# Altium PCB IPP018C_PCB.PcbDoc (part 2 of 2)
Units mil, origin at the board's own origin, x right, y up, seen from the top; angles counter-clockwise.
Board outline 3500 x 2700 mil, 4 copper layers (Top Layer, Mid-Layer 1, Mid-Layer 2, Bottom Layer), stack 90 mil thick; 62 components, 59 nets, 295 pads, 117 vias.
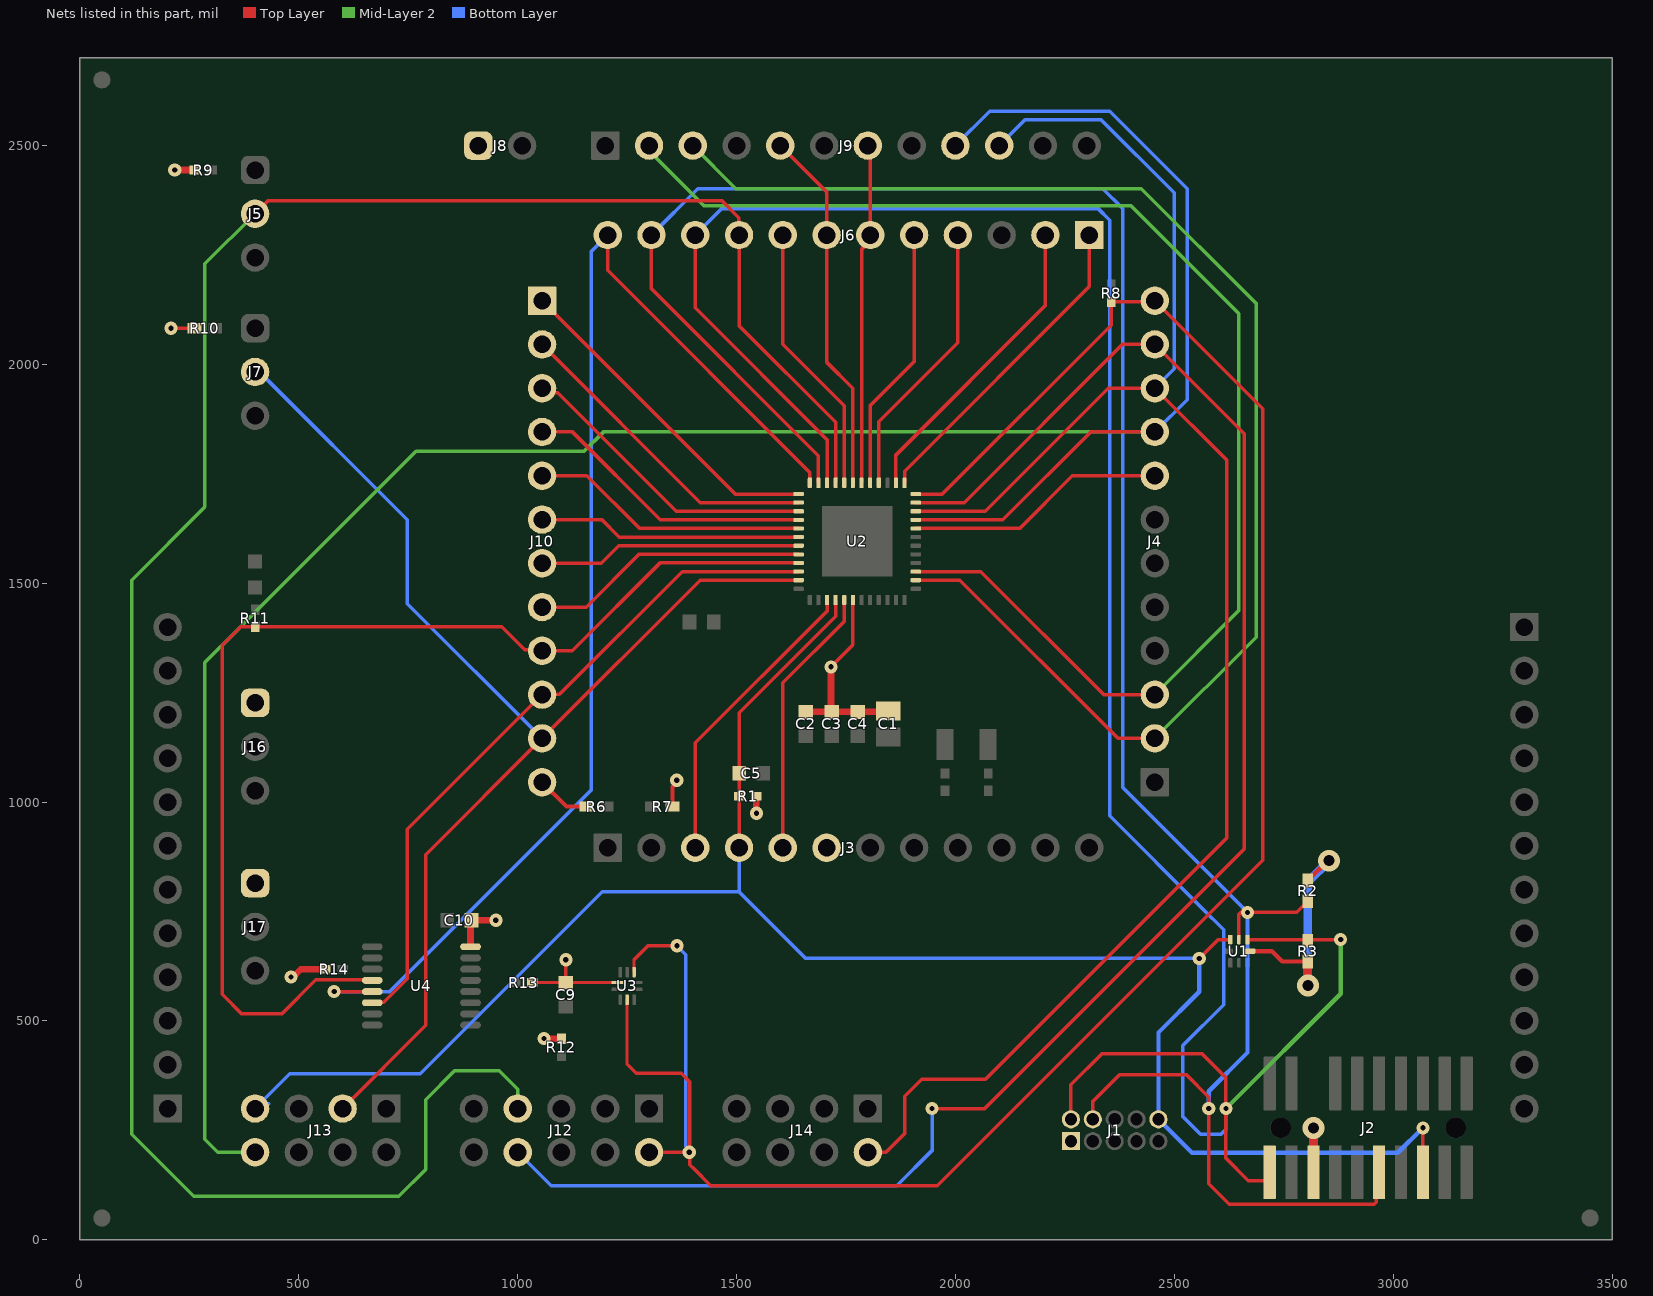
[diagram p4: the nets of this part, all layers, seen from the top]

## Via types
v1: diameter 30, hole 12, Top Layer to Bottom Layer, 102 vias
v2: diameter 19.68, hole 7.87, Top Layer to Bottom Layer, tented both sides, 12 vias
v3: diameter 50, hole 25, Top Layer to Bottom Layer, 2 vias
v4: diameter 50, hole 25, Top Layer to Bottom Layer, tented both sides, 1 vias

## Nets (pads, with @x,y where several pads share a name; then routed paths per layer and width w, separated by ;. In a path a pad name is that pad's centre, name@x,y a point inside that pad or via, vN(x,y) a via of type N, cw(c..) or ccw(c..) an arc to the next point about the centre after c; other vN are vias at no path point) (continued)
"PA13 UART3_RX": J6.4 U2.28 | length 641
  Top Layer w8: U2.28@1824.8,1729.45 1824.8,1868.75 2005.59,2049.54 J6.4@2005.59,2295.59
"PA14 UART3_TX": J6.5 U2.29 | length 607.8
  Top Layer w8: U2.29@1805.12,1729.45 1805.12,1906.14 1905.59,2006.61 J6.5@1905.59,2295.59
"PA15 I2C1_SCL": J6.6 J9.7 U2.30 | length 781.2
  Top Layer w8: U2.30@1785.43,1729.45 1785.43,2262.42 1805.59,2282.58 1805.59,2494.41 J9.7@1800,2500
"PA16 I2C1_SDA": J6.7 J9.5 U2.31 | length 839.2
  Top Layer w8: J9.5@1600,2500 1705.59,2394.41 J6.7@1705.59,2295.59 1705.59,2005.52 1765.75,1945.36 U2.31@1765.75,1729.45
PA17/A1_2: J6.8 U2.32 | length 624.3
  Top Layer w8: J6.8@1605.59,2295.59 1605.59,2046.09 1746.06,1905.62 U2.32@1746.06,1729.45
"PA18/A1_3 BSL SEL": J5.2 J6.9 J12.7 U2.33 | length 5265
  Top Layer w8: J5.2@400,2344.09 430.3,2374.39 1466.14,2374.39 1505.15,2335.38 1505.15,2296.04 J6.9@1505.59,2295.59 1505.59,2088.44 1726.38,1867.65 U2.33@1726.38,1729.45
  Mid-Layer 2 w8: J5.2@400,2344.09 285.43,2229.53 285.43,1674.31 118.11,1506.99 118.11,241.11 259.73,99.49 728.35,99.49 789.66,160.81 789.66,319.98 855.71,386.03 957.92,386.03 1000,343.95 J12.7@1000,300
"PA19 SWDIO": J1.2 J2.1 J6.10 R3.2 U1.1 U2.34 | length 5539.2
  Top Layer w8: J6.10@1405.59,2295.59 1405.59,2129.36 1706.69,1828.26 U2.34@1706.69,1729.45 ; J1.2@2263.8,275.42 2263.8,354 2335.36,425.56 2563.02,425.56 2618.11,370.47 v1(2618.11,300) 2618.11,186.22 2669.17,135.16 J2.1@2721.65,135.16 ; U1.1@2667.32,686.02 2802.17,686.02 R3.2@2805.12,683.07 2808.07,686.02 v1(2880.12,686.02)
  Mid-Layer 2 w10: v1(2618.11,300) 2880.12,562.01 v1(2880.12,686.02)
  Bottom Layer w8: J6.10@1405.59,2295.59 1466.04,2356.04 2325.75,2356.04 2352.36,2329.43 2352.36,968.52 2562.76,758.12 2612.85,708.03 2612.85,537.11 2519.68,443.94 2519.68,281.63 2559.92,241.39 2606.81,241.39 2618.11,252.69 v1(2618.11,300)
"PA20 SWCLK": J1.4 J2.11 J6.11 R2.2 U1.2 U2.35 | length 5326.7
  Top Layer w8: J6.11@1305.59,2295.59 1305.59,2172.75 1687.01,1791.34 U2.35@1687.01,1729.45 ; J1.4@2313.8,275.42 2314.24,275.85 2314.24,316.2 2374.94,376.91 2527.96,376.91 2578.74,326.13 v1(2578.74,300) 2578.74,127.95 2625.65,81.04 2956.6,81.04 2961.28,85.73 2961.28,147.8 J2.11@2967.91,154.43 ; U1.2@2647.64,686.02 2647.64,743.35 2652.32,748.03 v1(2667.32,748.03) 2779.53,748.03 R2.2@2805.12,773.62
  Bottom Layer w8: J6.11@1305.59,2295.59 1411.57,2401.57 2336.36,2401.57 2381.89,2356.04 2381.89,1033.46 v1(2667.32,748.03)
  Bottom Layer w10: v1(2578.74,300) 2578.74,339.35 2667.32,427.93 v1(2667.32,748.03)
PA21/A1_7/VREF-: J10.3 U2.39 | length 702.6
  Top Layer w8: J10.3@1055.59,1945.59 1066.23,1934.95 1091.86,1934.95 1362.33,1664.49 U2.39@1641.73,1664.49
PA22/A0_7: J10.4 U2.40 | length 669.3
  Top Layer w8: J10.4@1055.59,1845.59 1125.2,1845.59 1325.98,1644.8 U2.40@1641.73,1644.8
"PA23 VREF+": J10.7 U2.43 | length 602.8
  Top Layer w8: J10.7@1055.59,1545.59 1191.06,1545.59 1231.22,1585.75 U2.43@1641.73,1585.75
PA24/A0_3: J10.8 U2.44 | length 636
  Top Layer w8: J10.8@1055.59,1445.59 1156.5,1445.59 1276.97,1566.06 U2.44@1641.73,1566.06
"PA25 GUARDBAND": J10.9 R11.2 U2.45 U4.4 | length 2632.7
  Top Layer w8: U4.4@667.8,592.8 667.8,594.08 538.68,594.08 460.63,516.02 369.8,516.02 324.8,561.02 324.8,1358.27 366.85,1400.32 R11.2@400,1400.32 963.54,1400.32 1015.8,1348.06 1053.12,1348.06 J10.9@1055.59,1345.59 1124.39,1345.59 1325.18,1546.38 U2.45@1641.73,1546.38
"PA26/A0_1 INT TO HOST": J10.10 U2.46 U4.6 | length 1581.9
  Top Layer w8: U4.6@667.8,541.61 669.16,542.98 694.28,542.98 747.72,596.42 747.72,937.72 1056.09,1246.09 1095.38,1246.09 1375.98,1526.69 U2.46@1641.73,1526.69
"PA27/A0_0 I2C or UART/SPI": J7.2 J10.11 J13.3 U2.47 | length 2884.7
  Top Layer w8: J13.3@600,300 790,490 790,880 J10.11@1055.59,1145.59 1417.01,1507.01 U2.47@1641.73,1507.01
  Bottom Layer w8: J7.2@400,1982.7 410.12,1982.7 748.03,1644.79 748.03,1453.15 J10.11@1055.59,1145.59
"PA28 UART0_TX": J3.3 U2.3 | length 690.9
  Top Layer w8: J3.3@1405.59,895.59 1405.59,1135.23 1706.69,1436.33 U2.3@1706.69,1461.73
"PA31 UART0_RX": J3.5 U2.5 | length 624.3
  Top Layer w8: J3.5@1605.59,895.59 1605.59,1272.28 1746.06,1412.76 U2.5@1746.06,1461.73
"PB2 RESET": J4.2 J9.3 U2.14 | length 3221.8
  Top Layer w8: U2.14@1909.45,1507.01 2010.12,1507.01 2371.54,1145.59 J4.2@2455.59,1145.59
  Mid-Layer 2 w8: J9.3@1400,2500 1498.43,2401.57 2424.64,2401.57 2687.01,2139.21 2687.01,1377.01 J4.2@2455.59,1145.59
"PB3 OSS": J4.3 J9.2 U2.15 | length 3126.2
  Top Layer w8: U2.15@1909.45,1526.69 2058.18,1526.69 2339.28,1245.59 J4.3@2455.59,1245.59
  Mid-Layer 2 w8: J9.2@1300,2488.19 1426.24,2361.95 2401.83,2361.95 2647.64,2116.14 2647.64,1437.64 J4.3@2455.59,1245.59
  Bottom Layer w8: J9.2@1300,2488.19 J9.2@1300,2500
"PB6 SPI1_CS0": J4.8 U2.20 | length 596
  Top Layer w8: U2.20@1909.45,1625.12 2146.54,1625.12 2267.01,1745.59 J4.8@2455.59,1745.59
"PB7 PG1": J4.9 J9.9 J13.8 U2.21 | length 5455.9
  Top Layer w8: U2.21@1909.45,1644.8 2108.5,1644.8 2309.29,1845.59 J4.9@2455.59,1845.59
  Mid-Layer 2 w8: J13.8@400,200 314.96,200 285.43,229.53 285.43,1318.9 767.72,1801.18 1151.57,1801.18 1195.98,1845.59 J4.9@2455.59,1845.59
  Bottom Layer w8: J9.9@2000,2500 2078.74,2578.74 2352.36,2578.74 2529.53,2401.57 2529.53,1919.53 J4.9@2455.59,1845.59
"PB8 PG2": J4.10 J9.10 J14.2 U2.22 | length 3883.9
  Top Layer w8: J14.2@1800,200 1841.33,200 1884.17,242.84 1884.17,328.26 1923.02,367.11 2068.56,367.11 2620.33,918.88 2620.33,1780.85 J4.10@2455.59,1945.59 2349.13,1945.59 2068.03,1664.49 U2.22@1909.45,1664.49
  Bottom Layer w8: J9.10@2100,2500 2159.06,2559.06 2332.68,2559.06 2499.94,2391.79 2499.94,1989.94 J4.10@2455.59,1945.59
"PB9 SPI1_SCK": J4.11 J12.8 U2.23 | length 3999.3
  Top Layer w8: U2.23@1909.45,1684.17 2020.27,1684.17 2381.69,2045.59 J4.11@2455.59,2045.59 2659.7,1841.48 2659.7,892.99 2066.75,300.03 v1(1946.5,300.03)
  Bottom Layer w8: J12.8@1000,200 1076.48,123.52 1865.97,123.52 1946.5,204.04 v1(1946.5,300.03)
"PB14 SPI1_POCI": J4.12 J12.2 R8.1 U2.24 U3.4 U3.8 | length 4985.1
  Top Layer w7: 1250,401.22 U3.4@1250,548.5 ; U3.8@1265.75,611.5 1265.75,640
  Top Layer w8: 1250,401.22 1270.92,380.3 1373.39,380.3 1392.6,361.09 1392.6,172.36 ; 1265.75,640 1297.54,671.8 v1(1363.64,671.8) ; J12.2@1300,200 v1(1391.8,200) ; 1393.16,171.8 1402.69,162.27 1441.44,123.52 1958.71,123.52 2702.29,867.1 2702.29,1898.89 J4.12@2455.59,2145.59 ; U2.24@1909.45,1703.86 1969.84,1703.86 2355.59,2089.61 R8.1@2355.59,2143.28 J4.12@2453.28,2143.28
  Bottom Layer w8: v1(1363.64,671.8) 1384.17,651.27 1384.17,213.58 1391.8,205.95 v1(1391.8,200)
"PB15 SPI1_PICO/UART2_TX": J6.1 U2.25 | length 740.8
  Top Layer w8: U2.25@1883.86,1729.45 1883.86,1756.3 2305.59,2178.04 J6.1@2305.59,2295.59
"PB16 MUX_C": J6.2 U2.26 | length 707.6
  Top Layer w8: U2.26@1864.17,1729.45 1864.17,1793.08 2205.59,2134.5 J6.2@2205.59,2295.59
"PB17/A1_4 RESERVED": J6.12 U2.36 U4.5 | length 2905.9
  Top Layer w8: v1(580.71,567.2) U4.5@667.8,567.2 ; J6.12@1205.59,2295.59 1205.59,2214.82 1667.32,1753.09 U2.36@1667.32,1729.45
  Bottom Layer w8: v1(580.71,567.2) 707.35,567.2 1168.48,1028.34 1168.48,2258.48 J6.12@1205.59,2295.59
PB18/A1_5: J10.1 U2.37 | length 769.1
  Top Layer w8: J10.1@1055.59,2145.59 1084.07,2117.11 1497.32,1703.86 U2.37@1641.73,1703.86
PB19/A1_6: J10.2 U2.38 | length 735.8
  Top Layer w8: J10.2@1055.59,2045.59 1417.01,1684.17 U2.38@1641.73,1684.17
PB20/A0_6: J10.5 U2.41 | length 636
  Top Layer w8: J10.5@1055.59,1745.59 1157.95,1745.59 1278.43,1625.12 U2.41@1641.73,1625.12
PB24/A0_5: J10.6 U2.42 | length 602.8
  Top Layer w8: J10.6@1055.59,1645.59 1191.97,1645.59 1232.13,1605.43 U2.42@1641.73,1605.43
RST: C5.1 J1.10 J2.15 J3.4 J13.7 R1.1 U1.3 U2.4 | length 4474.6
  Top Layer w8: J3.4@1505.59,895.59 1505.91,895.91 R1.1@1505.91,1013.78 C5.1@1505.91,1065.59 1505.91,1204.53 1726.38,1425 U2.4@1726.38,1461.73 ; v1(2557.1,642.85) 2600.28,686.02 U1.3@2627.95,686.02 ; J2.15@3067.91,138.9 v1(3067.91,255.91)
  Bottom Layer w8: J13.7@400,300 J13.7@410.9,310.9 ; 430.94,310.9 J13.7@410.9,310.9 ; J3.4@1505.59,895.59 1505.59,795.58 ; v1(2557.1,642.85) 1658.33,642.85 1505.59,795.58 ; J13.7@410.9,310.9 479.61,379.61 777.13,379.61 1193.1,795.58 1505.59,795.58
  Bottom Layer w10: v1(2557.1,642.85) 2557.1,566.94 2463.8,473.65 J1.10@2463.8,275.42 2540.46,198.76 3010.77,198.76 v1(3067.91,255.91)
VDD: C1.2 C2.2 C3.2 C4.2 C9.2 C10.2 J1.1 J2.5 J3.6 J8.1 J10.12 J16.1 J17.1 R1.2 R2.1 R3.1 R6.2 R7.2 R9.2 R10.1 R12.1 R13.2 R14.2 U1.8 U2.6 U3.1 U4.16 | length 1970.8
  Top Layer w7: R13.2@1033.78,587.56 C9.2@1110,587.56 ; C9.2@1110.32,587.87 U3.1@1228.35,587.87
  Top Layer w8: v1(207.99,2082.7) R10.1@261.81,2082.7 ; C10.2@892.2,728.03 C10.2@894.17,730 ; R13.2@1033.46,587.87 R13.2@1033.78,587.56 ; v1(1060,460) v1@1060.32,459.68 ; v1(1110,640) C9.2@1110,587.56 C9.2@1110.32,587.87 ; v1(1715.8,1309.06) 1765.75,1359.01 U2.6@1765.75,1461.73
  Top Layer w10: J10.12@1055.59,1045.59 1111.34,989.84 R6.2@1156.38,989.84 ; R7.2@1353.62,989.84 1353.62,1034.89 1363.38,1044.65 v1(1363.38,1050.06) ; U1.8@2673.23,659.45 2723.03,659.45 2746.65,635.83 R3.1@2805.12,635.83 ; R2.1@2805.12,820.87 2850.39,866.14 v3(2853.74,866.14)
  Top Layer w15: v1(216.5,2444.09) R9.2@261.81,2444.09 ; v1(482.28,600.39) 486.34,600.39 504.33,618.39 R14.2@561.02,618.39 ; U4.16@892.2,669.57 C10.2@892.2,728.03 ; C10.2@894.17,730 v1(950,730) ; v1@1060.32,459.68 R12.1@1100,459.68 ; v1(1545.28,974.41) R1.2@1545.28,1013.78 ; C2.2@1657.87,1206.09 C3.2@1717.52,1206.09 ; v1(1715.8,1309.06) 1715.8,1207.82 C3.2@1717.52,1206.09 ; C1.2@1846.46,1208.06 1844.49,1206.09 C4.2@1777.17,1206.09 C3.2@1717.52,1206.09
  Top Layer w20: v4(2805.12,580.71) R3.1@2805.12,635.83 ; J2.5@2817.91,138.9 v3(2817.91,255.91)
  Bottom Layer w20: v4(2805.12,580.71) 2805.12,817.52 v3(2853.74,866.14)
pads on no net: FID1.1 FID2.1 FID3.1 J1.6 J1.8 J2. J2.2 J2.3 J2.4 J2.7 J2.9 J2.13 J2.14 J2.17 J2.18 J2.19 J9.11 J11.2 J11.3 J11.4 J11.5 J11.7 J11.8 J11.9 J11.10 J11.11 J13.1 J13.2 J13.5 J13.6 J14.1 J14.3 J14.4 J14.5 J14.6 J14.7 J14.8 J15.2 J15.3 J15.4 J15.5 J15.7 J15.8 J15.9 J15.10 J15.11 LBL1.0 SH-J1.0 SH-J2.0 SH-J3.0 SH-J4.0 SH-J5.0 U1.5 U1.6 U1.7 U4.9 U4.10 U4.11 U4.12

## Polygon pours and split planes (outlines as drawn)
GND_ISO on Mid-Layer 1 "MID-LAYER_1_GND_ISO_P012" (solid, remove dead copper, pour order 12): 50,2650 3450,2650 3450,50 50,50
VDD on Mid-Layer 2 "MID-LAYER_2_VDD_P013" (solid, pour order 13): 50,2650 50,50 3450,50 3450,2650
GND_ISO on Bottom Layer "BOTTOM_LAYER_GND_ISO_P015" (solid, remove dead copper, pour order 15): 3450,2650 3450,50 50,50 50,2650
GND_ISO on Top Layer "TOP_LAYER_GND_ISO_P014" (solid, remove dead copper, pour order 14): 47.09,2647.1 3447.09,2647.1 3447.09,47.1 47.09,47.1

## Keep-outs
Keep-Out Layer:
  lines w10: -5,0 ccw(c0,0) 0,-5 ; -5,0 ccw(c0,0) 0,-5 ; -5,0 -5,2700 ; -5,2700 cw(c0,2700) 0,2705 ; -5,2700 cw(c0,2700) 0,2705 ; 0,-5 3500,-5 ; 0,2705 3500,2705 ; 3500,-5 ccw(c3500,0) 3505,0 ; 3500,-5 ccw(c3500,0) 3505,0 ; 3500,2705 cw(c3500,2700) 3505,2700 ; 3500,2705 cw(c3500,2700) 3505,2700 ; 3505,0 3505,2700
  text ".Layer_Name" at 577,-858.49 h60

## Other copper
Top Layer:
  text ".Layer_Name" at 577,-858.49 h60
Bottom Layer:
  text ".Layer_Name" at 577,-858.49 h60

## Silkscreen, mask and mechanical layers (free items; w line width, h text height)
Top Overlay:
  lines w8: 1045,350 1045,390 1150,390 1150,350
  text "VDD/3.3V_ISO" at 735,2585 h72.83
  text "HIGH" at 462.6,2423.31 h72.83
  text "PIN 25" at 2290,2365 h70
  text "PIN 36" at 1035,2360 h70
  text "Reserved" at 462.6,2322.46 h72.83
  text "LOW" at 462.6,2220.73 h72.83
  text "PIN 37" at 787.4,2135.83 h70
  text "PIN 24" at 2519.43,2120 h70
  text "I2C" at 462.6,2061.71 h72.83
  text "'.PRJ_Number'.PCB_Rev" at 2871.39,1874.04 h108.27 r90
  text "UART/SPI" at 462.6,1861.27 h72.83
  text "PIN 48" at 795,1030 h70
  text "PIN 13" at 2519.43,996.1 h70
  text "PIN 1" at 1138.86,775 h70
  text "PIN 12" at 2300,775 h70
  text "XDS110" at 2819.64,441.39 h72.83
  text "(29)" at 315,390 h72.83
  text "(1)" at 1770,390 h72.83
  text "9" at 850,360 h72.83
  text "1" at 1330.53,357.71 h72.83
  text "2" at 1315,95 h72.83
  text "10" at 845,90 h72.83
  text "USB2ANY" at 950,80 h72.83
  text "(2)" at 1770,70 h72.83
  text "(30)" at 310,60 h72.83
  text ".Layer_Name" at 577,-858.49 h60
Bottom Overlay:
  text ".Layer_Name" at 577,-858.49 h60
Top Paste:
  text ".Layer_Name" at 577,-858.49 h60
Bottom Paste:
  text ".Layer_Name" at 577,-858.49 h60
Top Solder:
  text ".Layer_Name" at 577,-858.49 h60
  text ".Layer_Name" at 577,-858.49 h60
Bottom Solder:
  text ".Layer_Name" at 577,-858.49 h60
Drill Guide:
  text ".Layer_Name" at 577,-858.49 h60
M1 Board Outline:
  lines w10: 0,50 0,2700 3500,2700 3500,50 0,50
  text ".Layer_Name" at 577,-858.49 h60
M2 Board Dimensions:
  rectangle: 0,-275 125,-150
  rectangle: 125,-400 500,-275
  lines w7: 0,-275 1000,-275 ; 125,-400 125,-150 ; 250,-400 250,-150 ; 500,-400 500,-150 ; 750,-400 750,-150 ; 0,-400 1000,-400 1000,-150 0,-150 0,-400
  text ".Layer_Name" at 577,-858.49 h60
M3 3D STEP Top:
  text ".Layer_Name" at 577,-858.49 h60
M4 3D STEP Bottom:
  text ".Layer_Name" at 577,-858.49 h60
M5 Assembly Top:
  lines w10: -292,-930.17 6308,-930.17 ; -292,-726.83 6310,-726.83 ; -292,-523.5 -292,-1133.5 3713,-1133.5 6310,-1133.5 6310,-523.5 -291.5,-523.5 -291.5,-1133.5 1284,-1133.5 ; 2173,-1133.5 2173,-523.5 ; 3440,-726.83 3440,-523.5 ; 4280,-726.83 4280,-523.5 ; 4902,-1140 4902,-937.17
  text "COMPONENTS MARKED 'DNP' SHOULD NOT BE POPULATED." at 1153.5,-318.5 h40
  text "ASSEMBLY VARIANT:" at 1153,-434 h40
  text ".VariantName" at 2189,-434 h40
  text "PCB VIEWED FROM TOP SIDE" at -228.5,-655.67 h60
  text "BOARD #:" at 2248,-655.67 h60
  text ".PRJ_Number" at 2793.5,-655.67 h60
  text "REV:" at 3638,-655.67 h60
  text ".PCB_Rev" at 3929.5,-655.67 h60
  text "SVN REV:" at 4476,-655.67 h60
  text ".VersionControl_RevNumber" at 4982,-655.67 h60
  text "TID #:" at 2248,-859 h60
  text ".TID" at 2793.5,-859 h60
  text "PLOT NAME =" at -228.5,-1064.34 h60
  text ".plot_File_Name" at 577,-1064.34 h60
  text "GENERATED    :" at 2250,-1064.34 h60
  text ".Print_Date" at 3119.5,-1064.34 h60
  text ".Print_Time" at 3848.5,-1064.34 h60
  text "TEXAS INSTRUMENTS" at 5113,-1064.34 h60
M6 Assembly Bottom:
  lines w10: -292.5,-727.33 6309.5,-727.33 ; -290.5,-930.67 6309.5,-930.67 ; 1115.5,-1140.5 1115.5,-937.67 ; 1737.5,-727.33 1737.5,-524 ; 2577.5,-727.33 2577.5,-524 ; 3844.5,-1134 3844.5,-524 ; 4733.5,-1134 6309,-1134 6309,-524 -292.5,-524 -292.5,-1134 2304.5,-1134 6309.5,-1134 6309.5,-524
  text "COMPONENTS MARKED 'DNP' SHOULD NOT BE POPULATED." at 6102,-318 h40
  text ".VariantName" at 5058,-434 h40
  text "ASSEMBLY VARIANT:" at 6097,-434 h40
  text ".VersionControl_RevNumber" at 1035.5,-656.17 h60
  text "SVN REV:" at 1541.5,-656.17 h60
  text ".PCB_Rev" at 2088,-656.17 h60
  text "REV:" at 2379.5,-656.17 h60
  text ".PRJ_Number" at 3224,-656.17 h60
  text "BOARD #:" at 3769.5,-656.17 h60
  text "PCB VIEWED FROM BOTTOM SIDE" at 6246,-656.17 h60
  text ".TID" at 3224,-859.5 h60
  text "TID #:" at 3769.5,-859.5 h60
  text "TEXAS INSTRUMENTS" at 904.5,-1064.84 h60
  text ".Print_Time" at 2169,-1064.84 h60
  text ".Print_Date" at 2898,-1064.84 h60
  text "GENERATED    :" at 3767.5,-1064.84 h60
  text ".plot_File_Name" at 5440.5,-1064.84 h60
  text "PLOT NAME =" at 6246,-1064.84 h60
M9 Title Sheet:
  drawing of 57 lines, arcs and shapes, not listed
  text "1" at 739.84,8036.5 h70
  text "2" at 3235.5,8036.5 h70
  text "3" at 5724.84,8036.5 h70
  text "4" at 8231.51,8036.5 h70
  text "5" at 10730.5,8036.5 h70
  text "6" at 13235.5,8036.5 h70
  text "A" at -416.5,6893.5 h70
  text "A" at 14383.5,6893.5 h70
  text "B" at -416.5,4513.5 h70
  text "B" at 14383.5,4513.5 h70
  text "C" at -416.5,2138.5 h70
  text "C" at 14383.5,2138.5 h70
  text "PROJECT TITLE:" at 11343.5,277.5 h45
  text ".PRJ_Title" at 11393.5,144.17 h70
  text "DESIGNED FOR:" at 11343.5,-23.5 h45
  text ".PRJ_Customer" at 11393.5,-163.5 h70
  text "D" at -416.5,-231.5 h70
  text "D" at 14383.5,-231.5 h70
  text "FILE NAME:" at 11343.5,-323.5 h45
  text ".PCB_File_Name_No_Path" at 11393.5,-443.5 h70
  text "Texas Instruments (TI) and/or its licensors do not warrant the accuracy or completeness of this specification" at 6374,-605.34 h45
  text "ENGINEER:" at 11343.5,-613.5 h45
  text "LAYOUT BY:" at 12848.5,-613.5 h45
  text "or any information contained therein. TI and/or its licensors do not warrant that this design will meet" at 6329.01,-718 h45
  text ".PRJ_Engineer" at 11393.5,-768.49 h70
  text ".PCB_Layout" at 12899,-768.49 h70
  text "the specifications, will be suitable for your application or fit for any particular purpose, or will operate in" at 6329.01,-830.67 h45
  text ".Layer_Name" at 577,-858.49 h60
  text "ALTIUM DESIGNER VERSION:" at 12848.5,-923.5 h45
  text "an implementation. TI and/or its licensors do not warrant that the design is production worthy. You should" at 6329.01,-943.33 h45
  text "completely validate and test your design implementation to confirm the system functionality for your application." at 6374,-1056 h45
  text ".print_Scale" at 11393.5,-1056.83 h70
  text ".Application_BuildNumber" at 12899,-1056.83 h70
  text "1" at 739.84,-1263.5 h70
  text "2" at 3235.5,-1263.5 h70
  text "3" at 5724.84,-1263.5 h70
  text "4" at 8231.51,-1263.5 h70
  text "5" at 10730.5,-1263.5 h70
  text "6" at 13235.5,-1263.5 h70
M10 Fab Notes:
  drawing of 189 lines, arcs and shapes, not listed
  text "DESIGN INFORMATION" at 12382.02,6356.17 h60
  text "MIN. TRACK WIDTH:" at 11737.46,6224.05 h60
  text "8" at 12833.7,6224.05 h60
  text "MIL" at 12988.46,6224.05 h60
  text "7.874" at 12667.32,6102.36 h60
  text "MIN. CLEARANCE:" at 11737.46,6099.92 h60
  text "MIL" at 12988.46,6099.92 h60
  text "MIN. VIA PAD SIZE:" at 11737.46,5975.8 h60
  text "24" at 12803.71,5975.8 h60
  text "MIL" at 12988.46,5975.8 h60
  text "0.05mm (2MIL)" at 12432.46,5845.9 h60
  text "MINIMUM ANNULAR RING" at 11408.23,5837.67 h60
  text "EXTERNAL" at 13140.46,5837.67 h60
  text "PER" at 11608.23,5727.55 h60
  text "IPC-D-275 CLASS 2 LEVEL C" at 11828.23,5727.54 h60
  text "MIL, HOLES" at 13316.46,5627.07 h60
  text "+/-" at 12924,5618.48 h60
  text "+/-" at 13778,5618.48 h60
  text "REGISTRATION TOLERANCES:" at 11408.23,5617.42 h60
  text "METAL" at 12608,5617.42 h60
  text "5" at 13184.2,5617.42 h60
  text "3" at 14017.2,5617.42 h60
  text "MIL" at 14133.46,5617.42 h60
  text "HOLE SIZE TOLERANCE (UNLESS OTHERWISE SPECIFIED):" at 11408.23,5519.1 h60
  text "+/-" at 13778,5516.23 h60
  text "3" at 14017.2,5515.17 h60
  text "MIL" at 14133.46,5515.17 h60
  text "MATERIAL:" at 11333.46,5377.52 h60
  text "FR-4 High Tg" at 12319.9,5249 h60
  text "X" at 12175.46,5241.01 h60
  text "FR-4" at 11754.46,5236.49 h60
  text "OTHER" at 13242.46,5236.49 h60
  text "62 MIL (1.6mm) +/-10%" at 12074.56,5093.46 h60
  text "X" at 11954.46,5091.01 h60
  text "THICKNESS:" at 11408.23,5085.24 h60
  text "OTHER" at 13359.46,5085.24 h60
  text "TOLERANCE:" at 11408.23,4946.92 h60
  text "X" at 12256.46,4946.92 h60
  text "ANSI IPC-6012 TYPE 3 CLASS 2" at 12434.48,4946.92 h60
  text "OTHER +/-" at 12434.46,4802.73 h60
  text "BOW & TWIST:" at 11408.23,4657.54 h60
  text "X" at 12256.46,4657.54 h60
  text "ANSI IPC-6012 TYPE 3 CLASS 2" at 12434.48,4657.54 h60
  text "OTHER +/-" at 12434.46,4510.85 h60
  text "DRILLING:" at 11333.46,4380.23 h60
  text "NC_DRILL FILES" at 13094.46,4275.04 h60
  text "REFERENCE:" at 11408.23,4271.1 h60
  text "X" at 12065.46,4271.01 h60
  text "AS SHOWN" at 12243.46,4271.1 h60
  text "X" at 12966.46,4271.1 h60
  text "OTHER" at 13392.46,4128.85 h60
  text "PTH COPPER THICKNESS:" at 11407.91,4125.32 h60
  text "X" at 12547.14,4125.32 h60
  text "20-30 um" at 12675.14,4125.32 h60
  text "BOARD FINISH:" at 11333.46,3977.73 h60
  text "SILKSCREEN:" at 11488.68,3867.6 h60
  text "X" at 12446.46,3867.6 h60
  text "TOP" at 12563.46,3867.6 h60
  text "X" at 12956.46,3867.6 h60
  text "BOTTOM" at 13074.46,3867.6 h60
  text "SILKSCREEN COLOR:" at 11488.68,3712.41 h60
  text "X" at 12445.46,3712.41 h60
  text "WHITE" at 12563.46,3712.41 h60
  text "OTHER" at 13074.46,3712.41 h60
  text "X" at 12576.46,3568.96 h60
  text "GREEN" at 12694.46,3568.96 h60
  text "OTHER" at 13312.46,3568.96 h60
  text "SOLDER RESIST COLOR:" at 11488.68,3562.1 h60
  text "X" at 12576.46,3414.71 h60
  text "MATTE" at 12694.46,3414.71 h60
  text "SEMI-GLOSS" at 13312,3414.07 h60
  text "IMMERSION GOLD (ENIG)" at 12394.46,3241.94 h60
  text "ENEPIG" at 13732,3234.72 h60
  text "SURFACE FINISH:" at 11333.46,3233.72 h60
  text "X" at 12216.46,3233.72 h60
  text "IMM. TIN/SILVER OR EQUIV" at 11663,3096.4 h60
  text "OTHER" at 13094.46,3092.47 h60
  text "ARRAY/PANEL:" at 11333.46,2937.09 h60
  text "CUT AND TRIM PER M1 BOARD OUTLINE" at 12394.46,2928.87 h60
  text "N.C. ROUTE" at 12394.46,2792.9 h60
  text "X" at 13082.46,2792.9 h60
  text "V. SCORE" at 13260.46,2792.9 h60
  text "CERTIFICATION:" at 11333.46,2663.77 h60
  text "MATERIALS AND WORKMANSHIP FOR ALL PCBS" at 12058.46,2663.77 h60
  text "TO MEET OR EXCEED THE REQUIREMENTS OF:" at 12058.46,2569.71 h60
  text "X" at 11695.97,2441.08 h60
  text "ANSI IPC-A-600F CLASS ->" at 11823.96,2441.08 h60
  text "X" at 13471.97,2441.08 h60
  text "2" at 13581.96,2441.08 h60
  text "1" at 13266.96,2439.58 h60
  text "3" at 13935.96,2439.58 h60
  text "X" at 12507.97,2293.39 h60
  text "RoHS" at 12635.96,2293.39 h60
  text "OTHER" at 13280.36,2293.39 h60
  text "PER ORDER" at 13677.42,2293.39 h60
  text "ALL BOARDS MUST MEET OR EXCEED UL94-V0 REQUIREMENTS." at 11361,2139.57 h60
  text "PCB MUST BEAR THE UL94V-0 UL REGISTERED MATERIAL ID NUMBER" at 11361,2023.5 h60
  text "ADDITIONAL REQUIREMENTS:" at 11333.46,1854.08 h60
  text "MICROSECTION:" at 11408.23,1746.95 h60
  text "YES" at 12313.96,1746.95 h60
  text "REQUIRED" at 13175.46,1602.62 h60
  text "BARE BOARD ELEC. TEST:" at 11408.23,1599.76 h60
  text "NONE" at 12713.96,1599.76 h60
  text "X" at 13057.46,1599.76 h60
  text "PER ORDER" at 13767.46,1599.76 h60
  text "XX MIL VIAS REQUIRE NON-CONDUCTIVE FILL AND PLANARIZE" at 11576.38,1394.82 h59
  text "XX MIL VIAS REQUIRE CONDUCTIVE FILL AND PLANARIZE" at 11584.38,1290.84 h60
  text "OUTER XX MIL TRACES REQUIRE 50 OHM SINGLE-ENDED IMPEDANCE" at 11583.39,1127.46 h58
  text "LAYER 2 & 3 (INNER LAYERS) XX MIL WIDE, XX MIL SPACE / TRACES REQUIRE 100 OHM DIFFERENTIAL IMPEDANCE" at 11575.39,891.74 h60
  text ".Layer_Name" at 577,-858.49 h60
M11 Gerber Information:
  lines w10: -292,-930.17 6308,-930.17 ; -292,-726.83 6310,-726.83 ; -292,-523.5 -292,-1133.5 3713,-1133.5 6310,-1133.5 6310,-523.5 -291.5,-523.5 -291.5,-1133.5 1284,-1133.5 ; 2173,-1133.5 2173,-523.5 ; 3440,-726.83 3440,-523.5 ; 4280,-726.83 4280,-523.5 ; 4902,-1140 4902,-937.17
  text "ALL ARTWORK VIEWED FROM TOP SIDE" at -228.5,-655.67 h60
  text "BOARD #:" at 2248,-655.67 h60
  text ".PRJ_Number" at 2793.5,-655.67 h60
  text "REV:" at 3638,-655.67 h60
  text ".PCB_Rev" at 3929.5,-655.67 h60
  text "SVN REV:" at 4476,-655.67 h60
  text ".VersionControl_RevNumber" at 4982,-655.67 h60
  text "LAYER NAME =" at -228.5,-858.49 h60
  text "TID #:" at 2248,-859 h60
  text ".TID" at 2793.5,-859 h60
  text "PLOT NAME =" at -228.5,-1064.34 h60
  text ".plot_File_Name" at 577,-1064.34 h60
  text "GENERATED    :" at 2250,-1064.34 h60
  text ".Print_Date" at 3119.5,-1064.34 h60
  text ".Print_Time" at 3848.5,-1064.34 h60
  text "TEXAS INSTRUMENTS" at 5113,-1064.34 h60
M12 Stackup:
  drawing of 295 lines, arcs and shapes, not listed
  text "Layer" at 9801.59,7904.94 h40
  text "Name" at 10081.54,7904.94 h40
  text "Material" at 10708.03,7904.94 h40
  text "Thickness" at 11287.88,7904.94 h40
  text "Constant" at 11727.77,7904.94 h40
  text "Board Layer Stack" at 12114.34,7904.94 h40
  text "Top Overlay" at 10081.54,7824.94 h40
  text "Top Solder" at 10081.54,7744.94 h40
  text "Solder Resist" at 10708.03,7744.94 h40
  text "0.40mil" at 11287.88,7744.94 h40
  text "3.5" at 11727.77,7744.94 h40
  text "1" at 9801.59,7664.94 h40
  text "Top Layer" at 10081.54,7664.94 h40
  text "1.40mil" at 11287.88,7664.94 h40
  text "Dielectric1" at 10081.54,7584.94 h40
  text "FR-4 High Tg" at 10708.03,7584.94 h40
  text "59.20mil" at 11287.88,7584.94 h40
  text "4.8" at 11727.77,7584.94 h40
  text "2" at 9801.59,7504.94 h40
  text "Mid-Layer 1" at 10081.54,7504.94 h40
  text "1.40mil" at 11287.88,7504.94 h40
  text "Dielectric3" at 10081.54,7424.94 h40
  text "FR-4" at 10708.03,7424.94 h40
  text "12.60mil" at 11287.88,7424.94 h40
  text "4.8" at 11727.77,7424.94 h40
  text "3" at 9801.59,7344.94 h40
  text "Mid-Layer 2" at 10081.54,7344.94 h40
  text "1.40mil" at 11287.88,7344.94 h40
  text "Dielectric2" at 10081.54,7264.94 h40
  text "FR-4" at 10708.03,7264.94 h40
  text "12.60mil" at 11287.88,7264.94 h40
  text "4.8" at 11727.77,7264.94 h40
  text "4" at 9801.59,7184.94 h40
  text "Bottom Layer" at 10081.54,7184.94 h40
  text "1.40mil" at 11287.88,7184.94 h40
  text "Bottom Solder" at 10081.54,7104.94 h40
  text "Solder Resist" at 10708.03,7104.94 h40
  text "0.40mil" at 11287.88,7104.94 h40
  text "3.5" at 11727.77,7104.94 h40
  text "Bottom Overlay" at 10081.54,7024.94 h40
  text ".Layer_Name" at 577,-858.49 h60
M13 Component Bodies Top:
  text ".Layer_Name" at 577,-858.49 h60
M14 Component Bodies Bottom:
  text ".Layer_Name" at 577,-858.49 h60
M15 Courtyards Top:
  text ".Layer_Name" at 577,-858.49 h60
M16 Courtyards Bottom:
  text ".Layer_Name" at 577,-858.49 h60
Drill Drawing:
  circle w10: c5338.85,3268.64 r18.42
  lines w10: 5320.44,2918.7 5357.27,2918.7 5357.27,2955.54 5320.44,2955.54 5320.44,2918.7 ; 5320.44,3010.79 5329.64,3010.79 5329.64,3001.58 5348.06,3001.58 5348.06,3010.79 5357.27,3010.79 5357.27,3029.21 5348.06,3029.21 5348.06,3038.42 5329.64,3038.42 5329.64,3029.21 5320.44,3029.21 5320.44,3010.79 ; 5320.44,3093.67 5329.64,3093.67 5338.85,3084.46 5348.06,3093.67 5357.27,3093.67 5348.06,3102.88 5357.27,3112.09 5348.06,3112.09 5338.85,3121.3 5329.64,3112.09 5320.44,3112.09 5329.64,3102.88 5320.44,3093.67 ; 5320.44,3167.34 5338.85,3176.55 5357.27,3167.34 5348.06,3185.76 5357.27,3204.18 5338.85,3194.97 5320.44,3204.18 5329.64,3185.76 5320.44,3167.34 ; 5320.44,3369.94 5357.27,3369.94 5338.85,3333.1 5320.44,3369.94
  lines w12: 5286,2893.84 7440.32,2893.84 ; 5286,3391.12 7440.32,3391.12 ; 5511.24,2810.96 5511.24,3474 ; 5732.58,2810.96 5732.58,3474 ; 6156.95,2810.96 6156.95,3474 ; 6329.71,2810.96 6329.71,3474 ; 6579.82,2810.96 6579.82,3474 ; 7062.7,2810.96 7062.7,3474 ; 5286,2810.96 7440.32,2810.96 7440.32,3474 5286,3474 5286,2810.96
  text "Symbol" at 5335.73,3415.98 h48
  text "Quantity" at 5536.11,3415.98 h48
  text "Finished Hole Size" at 5757.44,3415.98 h48
  text "Plated" at 6181.81,3415.98 h48
  text "Hole Type" at 6354.57,3415.98 h48
  text "Drill Layer Pair" at 6604.68,3415.98 h48
  text "Hole Tolerance" at 7087.57,3415.98 h48
  text "2" at 5536.11,3333.1 h40
  text "47.00mil (1.194mm)" at 5757.44,3333.1 h40
  text "NPTH" at 6181.81,3333.1 h40
  text "Round" at 6354.57,3333.1 h40
  text "Top Layer - Bottom Layer" at 6604.68,3333.1 h40
  text "12" at 5536.11,3250.22 h40
  text "7.87mil (0.200mm)" at 5757.44,3250.22 h40
  text "PTH" at 6181.81,3250.22 h40
  text "Round" at 6354.57,3250.22 h40
  text "Top Layer - Bottom Layer" at 6604.68,3250.22 h40
  text "102" at 5536.11,3167.34 h40
  text "12.00mil (0.305mm)" at 5757.44,3167.34 h40
  text "PTH" at 6181.81,3167.34 h40
  text "Round" at 6354.57,3167.34 h40
  text "Top Layer - Bottom Layer" at 6604.68,3167.34 h40
  text "3" at 5536.11,3084.46 h40
  text "25.00mil (0.635mm)" at 5757.44,3084.46 h40
  text "PTH" at 6181.81,3084.46 h40
  text "Round" at 6354.57,3084.46 h40
  text "Top Layer - Bottom Layer" at 6604.68,3084.46 h40
  text "10" at 5536.11,3001.58 h40
  text "27.95mil (0.710mm)" at 5757.44,3001.58 h40
  text "PTH" at 6181.81,3001.58 h40
  text "Round" at 6354.57,3001.58 h40
  text "Top Layer - Bottom Layer" at 6604.68,3001.58 h40
  text "124" at 5536.11,2918.7 h40
  text "40.00mil (1.016mm)" at 5757.44,2918.7 h40
  text "PTH" at 6181.81,2918.7 h40
  text "Round" at 6354.57,2918.7 h40
  text "Top Layer - Bottom Layer" at 6604.68,2918.7 h40
  text "253 Total" at 5536.11,2835.82 h40
  text ".Layer_Name" at 577,-858.49 h60
M17 Embedded Cavity:
  text ".Layer_Name" at 577,-858.49 h60
M18 Embedded Assembly:
  text ".Layer_Name" at 577,-858.49 h60
M19 Embedded Keepout:
  text ".Layer_Name" at 577,-858.49 h60

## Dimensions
0,-400 to 1000,-400 on M2 Board Dimensions
0,0 to 0,2700 on M2 Board Dimensions
0,0 to 3500,0 on M2 Board Dimensions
